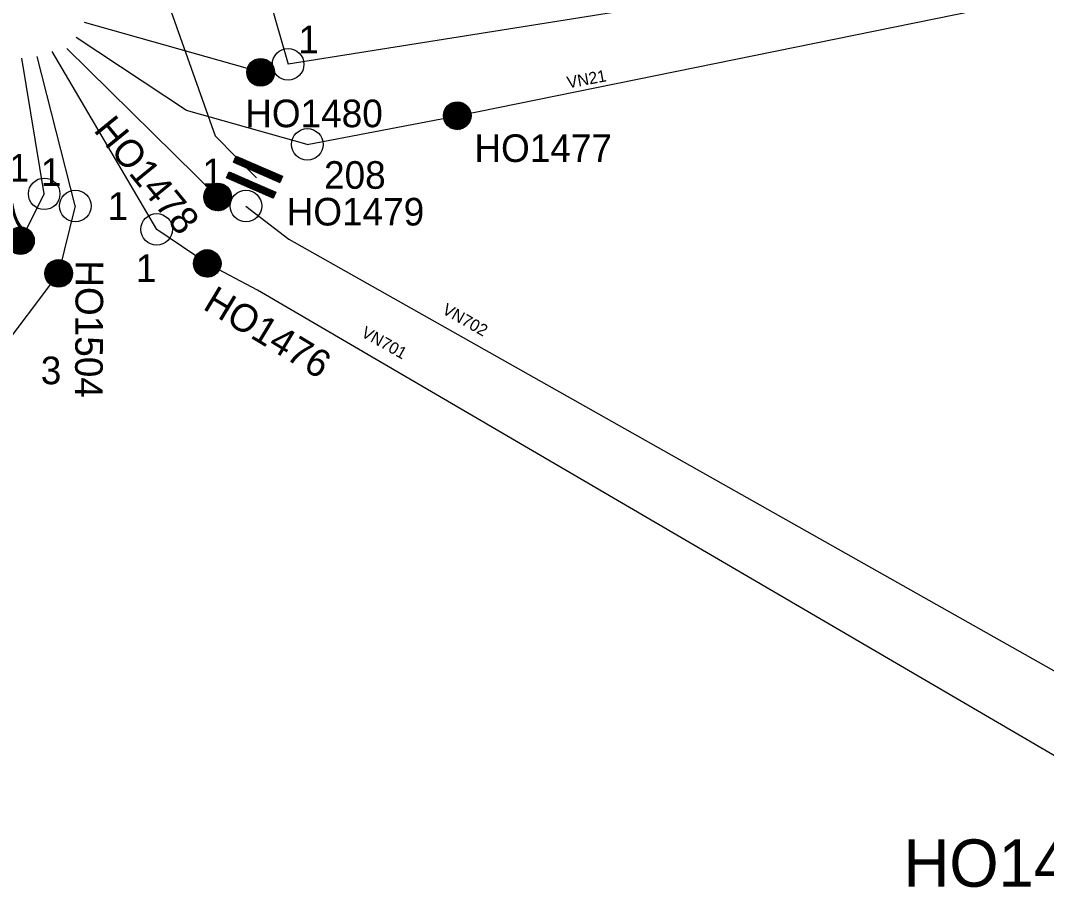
# Model space of a CAD drawing. Extents: x -546092 to -542700, y -1196659 to -1193917.
# Drawn here: x -545218 to -543918, y -1195926 to -1194828 of the extents above; entities that cross this region are included whole.
import ezdxf

# ---------------------------------------------------------------- set-up
doc = ezdxf.new("R2010")
doc.units = 0
for name, color, linetype in [('Default', 7, 'Continuous'), ('Vrstva 1', 7, 'Continuous'), ('Vrstva 2', 7, 'Continuous'), ('Vrstva 5', 7, 'Continuous')]:
    doc.layers.add(name, color=color, linetype=linetype)

# ---------------------------------------------------------------- blocks, each defined once
blk = doc.blocks.new('PS100')
at = {"layer": 'Default'}
for p, q in [((-17.5, -0.7), (0.7, 17.5)), ((-17.5, 0.7), (-0.7, 17.5)), ((-17.4, -2), (2, 17.4)), ((-17.3, 2.2), (-2.2, 17.3)), ((-17.2, -3.3), (3.3, 17.2)), ((-17, 4), (-4, 17)), ((-16.9, -4.4), (4.4, 16.9)), ((-16.6, -5.5), (5.5, 16.6)), ((-16.4, 6), (-6, 16.4)), ((-16.2, -6.5), (6.5, 16.2)), ((-15.8, -7.5), (7.5, 15.8)), ((-15.3, -8.4), (8.4, 15.3)), ((-15.2, 8.6), (-8.6, 15.2)), ((-14.8, -9.3), (9.3, 14.8)), ((-14.2, -10.2), (10.2, 14.2)), ((-13.6, -11), (11, 13.6)), ((-13, -11.7), (11.7, 13)), ((-12.3, -12.5), (12.5, 12.3)), ((-11.5, -13.2), (13.2, 11.5)), ((-10.8, -13.8), (13.8, 10.8)), ((-9.9, -14.4), (14.4, 9.9)), ((-9.1, -14.9), (14.9, 9.1)), ((-8.2, -15.5), (15.5, 8.2)), ((-7.2, -15.9), (15.9, 7.2)), ((-6.2, -16.3), (16.3, 6.2)), ((-5.2, -16.7), (16.7, 5.2)), ((-4.1, -17), (17, 4.1)), ((-2.9, -17.2), (17.2, 2.9)), ((-1.6, -17.4), (17.4, 1.6)), ((-0.3, -17.5), (17.5, 0.3)), ((1.1, -17.4), (17.4, -1.1)), ((2.7, -17.3), (17.3, -2.7)), ((4.5, -16.9), (16.9, -4.5)), ((6.7, -16.2), (16.2, -6.7)), ((9.7, -14.5), (14.5, -9.7))]:
    blk.add_line(p, q, dxfattribs=at)
blk.add_circle((0, 0), 17.5, dxfattribs=at)
blk = doc.blocks.new('PS110')
at = {"layer": 'Default'}
for p, q in [((-15.1, 21.8), (-7.6, 29.3)), ((-15.1, 23.2), (-9.1, 29.3)), ((-15.1, 24.6), (-10.5, 29.3)), ((-15.1, 26), (-11.9, 29.3)), ((-15.1, 27.4), (-13.3, 29.3)), ((-15.1, 28.8), (-14.7, 29.3)), ((-15.1, 20.4), (-6.6, 28.9)), ((-15.1, 18.9), (-6.6, 27.5)), ((-15.1, 17.5), (-6.6, 26.1)), ((-6.6, -35), (-6.6, 29.3)), ((6.6, 20.7), (15.2, 29.3)), ((6.6, 22.1), (13.7, 29.3)), ((6.6, 23.5), (12.3, 29.3)), ((6.6, 24.9), (10.9, 29.3)), ((6.6, 26.4), (9.5, 29.3)), ((6.6, 27.8), (8.1, 29.3)), ((6.6, 29.2), (6.7, 29.3)), ((6.6, 19.3), (15.2, 27.8)), ((6.6, 17.9), (15.2, 26.4)), ((-15.1, 16.1), (-6.6, 24.7)), ((-15.1, 14.7), (-6.6, 23.3)), ((-15.1, 13.3), (-6.6, 21.8)), ((-15.1, 11.9), (-6.6, 20.4)), ((-15.1, 10.5), (-6.6, 19)), ((-15.1, 9), (-6.6, 17.6)), ((-15.1, 7.6), (-6.6, 16.2)), ((-15.1, 6.2), (-6.6, 14.8)), ((-15.1, 4.8), (-6.6, 13.4)), ((6.6, 16.5), (15.2, 25)), ((6.6, 15), (15.2, 23.6)), ((6.6, 13.6), (15.2, 22.2)), ((6.6, 12.2), (15.2, 20.8)), ((6.6, 10.8), (15.2, 19.4)), ((6.6, 9.4), (15.2, 18)), ((6.6, 8), (15.2, 16.5)), ((6.6, 6.6), (15.2, 15.1)), ((6.6, 5.1), (15.2, 13.7)), ((-15.1, 3.4), (-6.6, 11.9)), ((-15.1, 2), (-6.6, 10.5)), ((-15.1, 0.6), (-6.6, 9.1)), ((-15.1, -0.9), (-6.6, 7.7)), ((-15.1, -2.3), (-6.6, 6.3)), ((-15.1, -3.7), (-6.6, 4.9)), ((-15.1, -5.1), (-6.6, 3.5)), ((-15.1, -6.5), (-6.6, 2.1)), ((-15.1, -7.9), (-6.6, 0.6)), ((6.6, 3.7), (15.2, 12.3)), ((6.6, 2.3), (15.2, 10.9)), ((6.6, 0.9), (15.2, 9.5)), ((6.6, -0.5), (15.2, 8.1)), ((6.6, -1.9), (15.2, 6.6)), ((6.6, -3.3), (15.2, 5.2)), ((6.6, -4.8), (15.2, 3.8)), ((6.6, -6.2), (15.2, 2.4)), ((6.6, -7.6), (15.2, 1)), ((-15.1, -9.3), (-6.6, -0.8)), ((-15.1, -10.8), (-6.6, -2.2)), ((-15.1, -12.2), (-6.6, -3.6)), ((-15.1, -13.6), (-6.6, -5)), ((-15.1, -15), (-6.6, -6.4)), ((-15.1, -16.4), (-6.6, -7.8)), ((-15.1, -17.8), (-6.6, -9.3)), ((-15.1, -19.2), (-6.6, -10.7)), ((-15.1, -20.7), (-6.6, -12.1)), ((6.6, -9), (15.2, -0.4)), ((6.6, -10.4), (15.2, -1.8)), ((6.6, -11.8), (15.2, -3.3)), ((6.6, -13.2), (15.2, -4.7)), ((6.6, -14.7), (15.2, -6.1)), ((6.6, -16.1), (15.2, -7.5)), ((6.6, -17.5), (15.2, -8.9)), ((6.6, -18.9), (15.2, -10.3)), ((6.6, -20.3), (15.2, -11.7)), ((-15.1, -22.1), (-6.6, -13.5)), ((-15.1, -23.5), (-6.6, -14.9)), ((-15.1, -24.9), (-6.6, -16.3)), ((-15.1, -26.3), (-6.6, -17.7)), ((-15.1, -27.7), (-6.6, -19.2)), ((-15.1, -29.1), (-6.6, -20.6)), ((-15.1, -30.6), (-6.6, -22)), ((-15.1, -32), (-6.6, -23.4)), ((-15.1, -33.4), (-6.6, -24.8)), ((6.6, -21.7), (15.2, -13.2)), ((6.6, -23.1), (15.2, -14.6)), ((6.6, -24.6), (15.2, -16)), ((6.6, -26), (15.2, -17.4)), ((6.6, -27.4), (15.2, -18.8)), ((6.6, -28.8), (15.2, -20.2)), ((6.6, -30.2), (15.2, -21.6)), ((6.6, -31.6), (15.2, -23.1)), ((6.6, -33), (15.2, -24.5)), ((6.6, -34.5), (15.2, -25.9)), ((-15.1, -34.8), (-6.6, -26.2)), ((-13.9, -35), (-6.6, -27.6)), ((-12.5, -35), (-6.6, -29.1)), ((-11.1, -35), (-6.6, -30.5)), ((-9.6, -35), (-6.6, -31.9)), ((-8.2, -35), (-6.6, -33.3)), ((-6.8, -35), (-6.6, -34.7)), ((7.5, -35), (15.2, -27.3)), ((8.9, -35), (15.2, -28.7)), ((10.3, -35), (15.2, -30.1)), ((11.7, -35), (15.2, -31.5)), ((13.2, -35), (15.2, -33)), ((14.6, -35), (15.2, -34.4))]:
    blk.add_line(p, q, dxfattribs=at)
for points in [[(-6.6, 29.3), (-6.6, -35), (-15.1, -35), (-15.1, 29.3)], [(15.2, 29.3), (15.2, -35), (6.6, -35), (6.6, 29.3)]]:
    blk.add_lwpolyline(points, close=True, dxfattribs=at)
blk = doc.blocks.new('PS140')
at = {"layer": 'Default'}
for p, q in [((-17.5, 0), (0, 17.5)), ((-17.4, -1.4), (1.4, 17.4)), ((-17.4, 1.5), (-1.5, 17.4)), ((-17.3, -2.6), (2.6, 17.3)), ((-17.2, 3.1), (-3.1, 17.2)), ((-17.1, -3.8), (3.8, 17.1)), ((-16.8, -4.9), (4.9, 16.8)), ((-16.8, 5), (-5, 16.8)), ((-16.4, -6), (6, 16.4)), ((-16, -7), (7, 16)), ((-15.9, 7.2), (-7.2, 15.9)), ((-15.6, -8), (8, 15.6)), ((-15.1, -8.9), (8.9, 15.1)), ((-14.5, -9.8), (9.8, 14.5)), ((-13.9, -10.6), (10.6, 13.9)), ((-13.8, 10.8), (-10.8, 13.8)), ((-13.3, -11.4), (11.4, 13.3)), ((-12.6, -12.1), (12.1, 12.6)), ((-11.9, -12.8), (12.8, 11.9)), ((-11.2, -13.5), (13.5, 11.2)), ((-10.4, -14.1), (14.1, 10.4)), ((-9.5, -14.7), (14.7, 9.5)), ((-8.6, -15.2), (15.2, 8.6)), ((-7.7, -15.7), (15.7, 7.7)), ((-6.7, -16.1), (16.1, 6.7)), ((-5.7, -16.5), (16.5, 5.7)), ((-4.6, -16.9), (16.9, 4.6)), ((-3.5, -17.1), (17.1, 3.5)), ((-2.3, -17.3), (17.3, 2.3)), ((-1, -17.5), (17.5, 1)), ((0.4, -17.5), (17.5, -0.4)), ((1.9, -17.4), (17.4, -1.9)), ((3.6, -17.1), (17.1, -3.6)), ((5.5, -16.6), (16.6, -5.5)), ((8, -15.6), (15.6, -8))]:
    blk.add_line(p, q, dxfattribs=at)
blk.add_circle((0, 0), 17.5, dxfattribs=at)
blk = doc.blocks.new('PS800')
at = {"layer": 'Vrstva 2'}
blk.add_circle((0, 0), 20, dxfattribs=at)

msp = doc.modelspace()

# ---------------------------------------------------------------- linework, layer by layer
at = {"layer": 'Vrstva 1'}
for points in [[(-543754.5, -1194704), (-544879, -1194883.4)], [(-544664.8, -1194948.5), (-543682.9, -1194748.4)], [(-544945.7, -1194749.9), (-545036.9, -1194789), (-544971.5, -1194974.1), (-544918.9, -1195027.4)], [(-544903.9, -1194796.4), (-544879, -1194883.4)], [(-544913.8, -1194893.5), (-545137, -1194830.5)], [(-544854.7, -1194984.9), (-545007.9, -1194942.1), (-545147.6, -1194849.3)], [(-544968.2, -1195051.5), (-545159.5, -1194863.4)], [(-545188, -1195047.5), (-545216.5, -1194875.7)], [(-545148.6, -1195062.8), (-545196.9, -1194873.6)], [(-545045.4, -1195092.6), (-545177.9, -1194867.3)], [(-544854.7, -1194984.9), (-544664.8, -1194948.5)], [(-545188, -1195047.5), (-545218, -1195106.9)], [(-545148.6, -1195062.8), (-545169.7, -1195148.3)], [(-544932.5, -1195062.9), (-544877.9, -1195104.9)], [(-544981.5, -1195135.7), (-545045.4, -1195092.6)], [(-544877.9, -1195104.9), (-543747.9, -1195742.8)], [(-544918, -1195169.6), (-544981.5, -1195135.7)], [(-545169.7, -1195148.3), (-545248.5, -1195252.1)], [(-543797.6, -1195824.2), (-544918, -1195169.6)]]:
    msp.add_lwpolyline(points, dxfattribs=at)

# ---------------------------------------------------------------- block references
at = {"layer": 'Vrstva 2'}
for name, p, rotation in [('PS100', (-544913.8, -1194893.5), -49.945966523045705), ('PS140', (-544664.8, -1194948.5), -17.488175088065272), ('PS110', (-544918.9, -1195027.4), -113.59339914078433), ('PS100', (-544968.2, -1195051.5), -64.28405003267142), ('PS140', (-545218, -1195106.9), 34.7114083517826), ('PS140', (-544981.5, -1195135.7), -59.17366938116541), ('PS140', (-545169.7, -1195148.3), 55.0153639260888)]:
    msp.add_blockref(name, p, dxfattribs=dict(at, rotation=rotation))
at = {"layer": 'Vrstva 5'}
for p, rotation in [((-544879, -1194883.4), -49.808330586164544), ((-544854.7, -1194984.9), -17.48817510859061), ((-545188, -1195047.5), 34.46903052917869), ((-545148.6, -1195062.8), 55.0153638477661), ((-544932.5, -1195062.9), -56.47723336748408), ((-545045.4, -1195092.6), -65.66144447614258)]:
    msp.add_blockref('PS800', p, dxfattribs=dict(at, rotation=rotation))

# ---------------------------------------------------------------- texts
at = {"layer": 'Vrstva 1'}
for s, rotation, p in [('VN21', 10.55, (-544524.3, -1194914)), ('VN702', 330.371, (-544685, -1195198.4)), ('VN701', 330.689, (-544787.6, -1195227.6))]:
    msp.add_text(s, height=15, rotation=rotation, dxfattribs=at).set_placement(p)
at = {"layer": 'Vrstva 2'}
for s, height, p in [('HO1480', 35, (-544933.4, -1194963.1)), ('HO1477', 35, (-544643.1, -1195007.1)), ('HO1479', 35, (-544880.9, -1195087.6)), ('HO1473', 60, (-544099.4, -1195925.4))]:
    msp.add_text(s, height=height, dxfattribs=at).set_placement(p)
for s, rotation, p in [('HO1478', 309.221, (-545126.4, -1194967.1)), ('HO1507', 41.009, (-545336.3, -1195195.6)), ('HO1504', 269.651, (-545148, -1195131.6)), ('HO1476', 328.891, (-544988.4, -1195192.7))]:
    msp.add_text(s, height=35, rotation=rotation, dxfattribs=at).set_placement(p)
at = {"layer": 'Vrstva 5'}
for s, p in [('1', (-544866.1, -1194869.6)), ('1', (-545233.1, -1195032)), ('1', (-545192.3, -1195037.4)), ('1', (-544987.7, -1195038)), ('208', (-544833.5, -1195041.1)), ('1', (-545107.6, -1195080.5)), ('1', (-545072, -1195159.3)), ('3', (-545192.3, -1195288.7))]:
    msp.add_text(s, height=35, dxfattribs=at).set_placement(p)

doc.saveas('drawing.dxf')
